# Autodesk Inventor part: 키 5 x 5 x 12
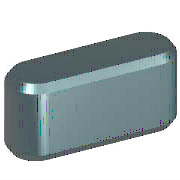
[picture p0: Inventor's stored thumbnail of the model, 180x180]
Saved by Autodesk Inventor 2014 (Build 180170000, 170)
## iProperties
IsCustomPart: 1
Created: 2012-02
Part Number: 키 5 x 5 x 12
Material: 강철, 연강
Description: 키 및 해당 키홈
Document SubType Name: Modeling
Standard: KS B 1311
Designer: mduedu
Standards Organization: KS
Language: ko-KR
Size Designation: 5 x 5 x 12
Categories: <MemberInstance><Categories><Category DisplayName="샤프트 부품" InternalName="7f7aeb1f-a693-4053-b835-cee3144e0d98" Mnemonic="SHFT"><Category DisplayName="키" Interna
Density: 7.86 g/cm^3
Mass: 2.11085 g
Surface Area: 2.43471 cm^2
Volume: 0.268556 cm^3
Appearance: Yellow
Author: mduedu
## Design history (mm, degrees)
sketch "스케치1"
  geometry: L1 (2.5, 2.5)-(9.5, 2.5); L2 (9.5, -2.5)-(2.5, -2.5); L3 (0, 9.4)-(0, -7.4) reference; L4 (-5, 0)-(30, 0) reference; L5 (12, 0)-(12, 7); A1 r 2.5 centre (2.5, 0) between (2.5, 2.5) and (2.5, -2.5); A2 r 2.5 centre (9.5, 0) between (9.5, -2.5) and (9.5, 2.5)
  constraints: 6 end point, 5 point on circle, 4 tangent, 3 point on line, 2 centre point, 1 horizontal, 1 parallel, 1 perpendicular
  dimensions: "d0" = 2.5 radius of A1 (= 0.5 x PB); "d13" = 2.5 radius of A2 (= 0.5 x PB); "d14" = 12 distance between parallel lines of L5 L3 (= NLG)
extrude "본체1" new body sketch "스케치1" taper "d3" = 0 deg; stored distance "d4" = 10
workplane "Work Plane3"
body "Solid1"
workplane "Work Plane1"
workplane "Work Plane2"
chamfer "모따기1" distance "d8" = 0.4 (= PHH); stored, may be unused: second distance "d9" = 0.4 (= PHH), angle "d15" = 45 deg
other parameters: "d1" = -3 (= -PNT), "d2" = 2 (= PH - PNT), "NLG" = 12 [user parameter; used in 3 equation terms], "PB" = 5 [user parameter; used in 2 equation terms], "PNT" = 3 [user parameter; used in 2 equation terms], "PH" = 5 [user parameter; used in 1 equation term], "PHH" = 0.4 [user parameter; used in 2 equation terms], "d10" = 0, "d16" = 0, "d17" = 0, "d18" = 0, "WDMIN" = 12 [user parameter], "PLB2" = 12 (= NLG) [user parameter], "WDMAX" = 17 [user parameter], "PLB1" = 12 (= NLG) [user parameter], "RR" = 0.16 [user parameter], "PUEB" = 2.3 [user parameter]
